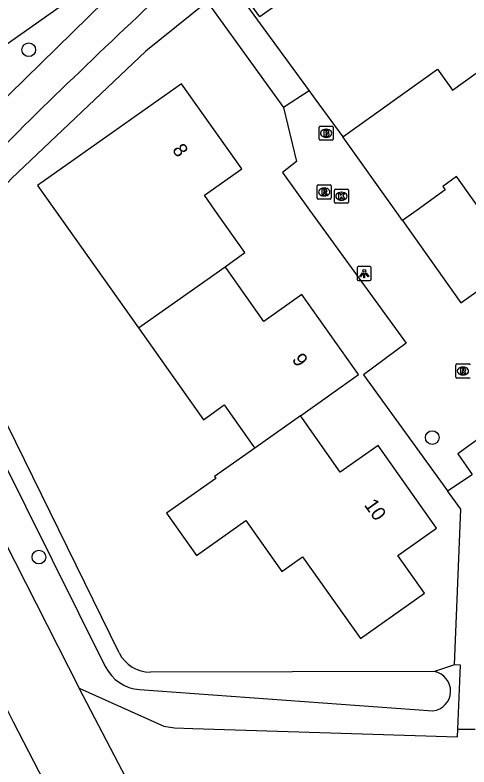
# Model space of a CAD drawing. Extents: x 158461 to 159795, y 387220 to 388672.
# Drawn here: x 159204.5 to 159236.8, y 387710.4 to 387763.8 of the extents above; entities that cross this region are included whole.
import ezdxf

# ---------------------------------------------------------------- set-up
doc = ezdxf.new("R2010")
doc.units = 0
for name, color, linetype in [('IMGEO_Berm_groen', 7, 'Continuous'), ('IMGEO_Boom', 7, 'Continuous'), ('IMGEO_Brandkraan', 7, 'Continuous'), ('IMGEO_Fietspad_gesloten', 7, 'Continuous'), ('IMGEO_Fietspad_open', 7, 'Continuous'), ('IMGEO_Kolk', 7, 'Continuous'), ('IMGEO_Lichtpunt', 7, 'Continuous'), ('IMGEO_Pand', 7, 'Continuous'), ('IMGEO_Pand_nummerreeks', 7, 'Continuous'), ('IMGEO_Rijbaan_lokaal_gesloten', 7, 'Continuous'), ('IMGEO_Rijbaan_lokaal_open', 7, 'Continuous'), ('IMGEO_Rioolput', 7, 'Continuous'), ('IMGEO_Voetpad_halfverhard', 7, 'Continuous'), ('IMGEO_Voetpad_open', 7, 'Continuous'), ('IMGEO_Waterloop', 7, 'Continuous')]:
    doc.layers.add(name, color=color, linetype=linetype)

msp = doc.modelspace()

# ---------------------------------------------------------------- linework, layer by layer
at = {"layer": 'IMGEO_Berm_groen'}
msp.add_lwpolyline([(159235.73, 387717.691), (159234.304, 387717.222)], dxfattribs=at)
at = {"layer": 'IMGEO_Boom'}
for centre in [(159205.5, 387761.384), (159234.149, 387733.837), (159206.219, 387725.353)]:
    msp.add_circle(centre, 0.489, dxfattribs=at)
at = {"layer": 'IMGEO_Brandkraan'}
for p, q in [((159226.186, 387755.954), (159227.038, 387755.954)), ((159226.111, 387755.028), (159226.111, 387755.88)), ((159226.599, 387755.734), (159226.624, 387755.734)), ((159227.112, 387755.88), (159227.112, 387755.028)), ((159227.038, 387754.954), (159226.186, 387754.954)), ((159226.622, 387755.174), (159226.597, 387755.174))]:
    msp.add_line(p, q, dxfattribs=at)
for points in [[(159226.186, 387755.954), (159227.038, 387755.954)], [(159226.111, 387755.028), (159226.111, 387755.88)], [(159226.459, 387755.654), (159226.459, 387755.254), (159226.672, 387755.254)], [(159226.69, 387755.654), (159226.459, 387755.654)], [(159226.638, 387755.573), (159226.584, 387755.573), (159226.584, 387755.497)], [(159226.584, 387755.497), (159226.637, 387755.497)], [(159226.646, 387755.421), (159226.584, 387755.421), (159226.584, 387755.34)], [(159227.112, 387755.88), (159227.112, 387755.028)], [(159227.038, 387754.954), (159226.186, 387754.954)], [(159226.584, 387755.34), (159226.646, 387755.34)]]:
    msp.add_lwpolyline(points, dxfattribs=at)
for centre, radius, start, end in [((159226.188, 387755.878), 0.0765, 91.552, 178.448), ((159226.188, 387755.878), 0.0765, 91.552, 178.448), ((159227.036, 387755.878), 0.0765, 1.552, 88.448), ((159227.036, 387755.878), 0.0765, 1.552, 88.448), ((159226.639, 387755.535), 0.0379, 267.8285, 90.9355), ((159226.647, 387755.38), 0.0404, 269.8759, 90.5077), ((159226.694, 387755.509), 0.145, 59.4692, 91.5367), ((159226.719, 387755.556), 0.0922, 285.5137, 58.1501), ((159226.724, 387755.364), 0.105, 301.3115, 78.989), ((159226.188, 387755.03), 0.0765, 181.552, 268.448), ((159226.188, 387755.03), 0.0765, 181.552, 268.448), ((159226.678, 387755.505), 0.251, 268.6676, 293.5347), ((159227.036, 387755.03), 0.0765, 271.552, 358.448), ((159227.036, 387755.03), 0.0765, 271.552, 358.448)]:
    msp.add_arc(centre, radius, start, end, dxfattribs=at)
for centre, major_axis, ratio, start_param, end_param in [((159226.598, 387755.454), (-0.387, 0.002), 0.722429, 4.712389, 7.853982), ((159226.623, 387755.454), (-0.39, 0.002), 0.717154, 1.570796, 4.712389)]:
    msp.add_ellipse(centre, major_axis=major_axis, ratio=ratio, start_param=start_param, end_param=end_param, dxfattribs=at)
at = {"layer": 'IMGEO_Fietspad_gesloten'}
for points in [[(159203.744, 387726.53), (159209.072, 387716.044)], [(159305.871, 387516.378), (159305.772, 387516.604), (159303.42, 387520.816), (159263.501, 387599.257), (159204.425, 387713.621), (159204.015, 387714.421), (159199.05, 387724.103)], [(159214.062, 387706.489), (159209.072, 387716.044)]]:
    msp.add_lwpolyline(points, dxfattribs=at)
at = {"layer": 'IMGEO_Fietspad_open'}
msp.add_lwpolyline([(159214.491, 387768.328), (159213.131, 387767.053), (159199.59, 387753.792), (159198.894, 387753.089), (159198.822, 387753.027)], dxfattribs=at)
for centre, radius, start, end in [((159441.931, 387520.228), 334.072, 132.45033, 134.17723), ((159347.221, 387613.579), 201.141, 133.35949, 138.92324)]:
    msp.add_arc(centre, radius, start, end, dxfattribs=at)
at = {"layer": 'IMGEO_Kolk'}
for p, q in [((159227.199, 387750.556), (159227.199, 387751.408)), ((159227.274, 387751.482), (159228.126, 387751.482)), ((159227.687, 387751.262), (159227.712, 387751.262)), ((159228.2, 387751.408), (159228.2, 387750.556)), ((159227.71, 387750.702), (159227.685, 387750.702)), ((159228.126, 387750.482), (159227.274, 387750.482))]:
    msp.add_line(p, q, dxfattribs=at)
for points in [[(159227.199, 387750.556), (159227.199, 387751.408)], [(159227.274, 387751.482), (159228.126, 387751.482)], [(159227.52, 387751.182), (159227.643, 387751.182), (159227.643, 387751.031), (159227.773, 387751.182), (159227.937, 387751.182), (159227.791, 387751.031), (159227.944, 387750.782), (159227.792, 387750.782), (159227.707, 387750.946), (159227.643, 387750.879), (159227.643, 387750.782), (159227.52, 387750.782), (159227.52, 387751.182)], [(159228.2, 387751.408), (159228.2, 387750.556)], [(159228.126, 387750.482), (159227.274, 387750.482)]]:
    msp.add_lwpolyline(points, dxfattribs=at)
for centre, start, end in [((159227.276, 387751.406), 91.552, 178.448), ((159227.276, 387751.406), 91.552, 178.448), ((159228.124, 387751.406), 1.552, 88.448), ((159228.124, 387751.406), 1.552, 88.448), ((159227.276, 387750.558), 181.552, 268.448), ((159227.276, 387750.558), 181.552, 268.448), ((159228.124, 387750.558), 271.552, 358.448), ((159228.124, 387750.558), 271.552, 358.448)]:
    msp.add_arc(centre, 0.0765, start, end, dxfattribs=at)
for centre, major_axis, ratio, start_param, end_param in [((159227.686, 387750.982), (-0.387, 0.002), 0.722429, 4.712389, 7.853982), ((159227.711, 387750.982), (-0.39, 0.002), 0.717154, 1.570796, 4.712389)]:
    msp.add_ellipse(centre, major_axis=major_axis, ratio=ratio, start_param=start_param, end_param=end_param, dxfattribs=at)
at = {"layer": 'IMGEO_Lichtpunt'}
for p, q in [((159228.821, 387745.886), (159228.821, 387745.079)), ((159228.821, 387745.886), (159228.821, 387745.079)), ((159229.723, 387745.981), (159228.915, 387745.981)), ((159229.723, 387745.981), (159228.915, 387745.981)), ((159229.817, 387745.079), (159229.817, 387745.886)), ((159229.817, 387745.079), (159229.817, 387745.886)), ((159228.915, 387744.985), (159229.723, 387744.985)), ((159228.915, 387744.985), (159229.723, 387744.985))]:
    msp.add_line(p, q, dxfattribs=at)
for points in [[(159229.195, 387745.55), (159229.234, 387745.522), (159229.046, 387745.26), (159229.008, 387745.287), (159229.195, 387745.55)], [(159229.297, 387745.502), (159229.344, 387745.502), (159229.344, 387745.18), (159229.297, 387745.18), (159229.297, 387745.502)], [(159229.407, 387745.522), (159229.445, 387745.549), (159229.632, 387745.287), (159229.593, 387745.259), (159229.407, 387745.522)]]:
    msp.add_lwpolyline(points, dxfattribs=at)
msp.add_circle((159229.32, 387745.684), 0.0994, dxfattribs=at)
for centre, start, end in [((159228.915, 387745.886), 90, 180), ((159228.915, 387745.886), 90, 180), ((159229.723, 387745.886), 0, 90), ((159229.723, 387745.886), 0, 90), ((159228.915, 387745.079), 180, 270), ((159228.915, 387745.079), 180, 270), ((159229.723, 387745.079), 270, 0), ((159229.723, 387745.079), 270, 360)]:
    msp.add_arc(centre, 0.0946, start, end, dxfattribs=at)
at = {"layer": 'IMGEO_Pand'}
for points in [[(159224.026, 387765.272), (159221.912, 387763.731), (159220.309, 387765.93), (159222.423, 387767.471), (159224.026, 387765.272)], [(159227.788, 387755.197), (159234.513, 387760.012), (159235.582, 387758.518), (159238.444, 387760.567), (159238.638, 387760.706)], [(159219.44, 387745.978), (159220.851, 387746.977), (159218.713, 387750), (159217.973, 387751.046), (159220.621, 387752.92), (159216.34, 387758.971), (159209.096, 387753.846), (159206.13, 387751.748), (159208.321, 387748.651), (159213.29, 387741.626)], [(159232.039, 387749.261), (159231.51, 387750), (159227.788, 387755.197)], [(159242.699, 387755.037), (159243.735, 387753.59), (159238.722, 387750), (159237.962, 387749.456), (159237.572, 387750), (159236.047, 387752.13), (159235.872, 387752.374), (159234.896, 387751.676), (159235.071, 387751.431), (159233.071, 387750), (159232.039, 387749.261)], [(159213.29, 387741.626), (159219.44, 387745.978)], [(159224.79, 387735.39), (159228.92, 387738.31), (159224.896, 387743.997), (159222.194, 387742.085), (159219.527, 387745.855), (159219.44, 387745.978)], [(159213.29, 387741.626), (159217.899, 387735.111), (159219.374, 387736.154), (159221.405, 387733.283), (159221.54, 387733.092)], [(159221.54, 387733.092), (159218.685, 387731.074), (159218.777, 387730.944), (159215.287, 387728.476), (159217.411, 387725.473), (159220.901, 387727.942), (159223.459, 387724.327), (159224.942, 387725.377), (159229.048, 387719.576), (159233.601, 387722.797), (159231.707, 387725.473), (159234.449, 387727.414), (159230.297, 387733.283), (159227.62, 387731.389), (159224.935, 387735.185), (159224.79, 387735.39)], [(159224.79, 387735.39), (159221.54, 387733.092)]]:
    msp.add_lwpolyline(points, dxfattribs=at)
at = {"layer": 'IMGEO_Rijbaan_lokaal_gesloten'}
msp.add_lwpolyline([(159196.748, 387756.729), (159202.425, 387760.735), (159214.068, 387768.944)], dxfattribs=at)
at = {"layer": 'IMGEO_Rijbaan_lokaal_open'}
for points in [[(159232.039, 387749.261), (159236.184, 387743.412), (159238.603, 387745.147), (159240.605, 387744.76), (159247.948, 387750), (159265.053, 387762.206), (159265.409, 387764.288), (159291.33, 387782.791), (159291.199, 387784.46), (159296.92, 387788.616), (159298.653, 387788.087), (159304.712, 387792.385), (159307.252, 387792.251), (159320.165, 387774.132), (159324.208, 387773.477), (159343.063, 387787.123), (159343.181, 387788.954)], [(159277.893, 387764.497), (159277.605, 387762.555), (159274.948, 387760.678), (159277.299, 387757.343), (159266.972, 387750), (159257.945, 387743.581), (159255.655, 387746.817), (159253.197, 387745.09), (159251.126, 387745.348), (159238.707, 387736.519), (159238.451, 387734.477), (159235.953, 387732.682), (159236.986, 387731.212)], [(159225.4, 387758.477), (159223.591, 387757.291)], [(159225.4, 387758.477), (159225.842, 387757.87), (159227.788, 387755.197)], [(159223.591, 387757.291), (159224.515, 387753.447), (159223.511, 387752.661), (159225.442, 387750), (159232.294, 387740.557), (159229.26, 387738.298), (159235.227, 387730.066)], [(159235.227, 387730.066), (159236.986, 387731.212)]]:
    msp.add_lwpolyline(points, dxfattribs=at)
at = {"layer": 'IMGEO_Rioolput'}
for p, q in [((159225.977, 387750.857), (159225.977, 387751.709)), ((159226.052, 387751.783), (159226.904, 387751.783)), ((159226.978, 387751.709), (159226.978, 387750.857)), ((159226.465, 387751.563), (159226.49, 387751.563)), ((159226.904, 387750.783), (159226.052, 387750.783)), ((159226.488, 387751.003), (159226.463, 387751.003)), ((159235.825, 387738.141), (159235.825, 387738.993)), ((159235.9, 387739.067), (159236.752, 387739.067)), ((159236.313, 387738.847), (159236.338, 387738.847)), ((159236.752, 387738.067), (159235.9, 387738.067)), ((159236.336, 387738.287), (159236.311, 387738.287))]:
    msp.add_line(p, q, dxfattribs=at)
for points in [[(159225.977, 387750.857), (159225.977, 387751.709)], [(159226.052, 387751.783), (159226.904, 387751.783)], [(159226.978, 387751.709), (159226.978, 387750.857)], [(159226.566, 387751.481), (159226.314, 387751.483), (159226.314, 387751.083)], [(159226.314, 387751.083), (159226.438, 387751.083), (159226.438, 387751.245), (159226.449, 387751.245)], [(159226.492, 387751.402), (159226.438, 387751.402), (159226.438, 387751.321)], [(159226.438, 387751.321), (159226.49, 387751.321)], [(159226.496, 387751.216), (159226.567, 387751.083), (159226.707, 387751.083), (159226.642, 387751.209)], [(159226.904, 387750.783), (159226.052, 387750.783)], [(159235.825, 387738.141), (159235.825, 387738.993)], [(159235.9, 387739.067), (159236.752, 387739.067)], [(159236.414, 387738.765), (159236.162, 387738.767), (159236.162, 387738.367)], [(159236.162, 387738.367), (159236.286, 387738.367), (159236.286, 387738.529), (159236.297, 387738.529)], [(159236.34, 387738.686), (159236.286, 387738.686), (159236.286, 387738.605)], [(159236.286, 387738.605), (159236.338, 387738.605)], [(159236.344, 387738.5), (159236.415, 387738.367), (159236.555, 387738.367), (159236.49, 387738.493)], [(159236.752, 387738.067), (159235.9, 387738.067)]]:
    msp.add_lwpolyline(points, dxfattribs=at)
for centre, radius, start, end in [((159226.054, 387751.707), 0.0765, 91.552, 178.448), ((159226.054, 387751.707), 0.0765, 91.552, 178.448), ((159226.902, 387751.707), 0.0765, 1.552, 88.448), ((159226.902, 387751.707), 0.0765, 1.552, 88.448), ((159226.448, 387751.192), 0.0533, 26.0293, 88.6989), ((159226.474, 387751.51), 0.19, 274.7715, 282.9687), ((159226.498, 387751.306), 0.0964, 77.0061, 93.1865), ((159226.512, 387751.363), 0.0378, 276.6634, 79.6772), ((159226.565, 387751.371), 0.109, 350.3612, 89.416), ((159226.563, 387751.371), 0.112, 277.5842, 350.9817), ((159226.547, 387751.156), 0.108, 29.5134, 73.7905), ((159226.054, 387750.859), 0.0765, 181.552, 268.448), ((159226.054, 387750.859), 0.0765, 181.552, 268.448), ((159226.902, 387750.859), 0.0765, 271.552, 358.448), ((159226.902, 387750.859), 0.0765, 271.552, 358.448), ((159235.902, 387738.991), 0.0765, 91.552, 178.448), ((159235.902, 387738.991), 0.0765, 91.552, 178.448), ((159236.75, 387738.991), 0.0765, 1.552, 88.448), ((159236.75, 387738.991), 0.0765, 1.552, 88.448), ((159236.296, 387738.476), 0.0533, 26.0293, 88.6989), ((159236.322, 387738.794), 0.19, 274.7715, 282.9687), ((159236.346, 387738.59), 0.0964, 77.0061, 93.1865), ((159236.36, 387738.647), 0.0378, 276.6634, 79.6772), ((159236.413, 387738.655), 0.109, 350.3612, 89.416), ((159236.411, 387738.655), 0.112, 277.5842, 350.9817), ((159236.395, 387738.44), 0.108, 29.5134, 73.7905), ((159235.902, 387738.143), 0.0765, 181.552, 268.448), ((159235.902, 387738.143), 0.0765, 181.552, 268.448), ((159236.75, 387738.143), 0.0765, 271.552, 358.448), ((159236.75, 387738.143), 0.0765, 271.552, 358.448)]:
    msp.add_arc(centre, radius, start, end, dxfattribs=at)
for centre, major_axis, ratio, start_param, end_param in [((159226.464, 387751.283), (-0.387, 0.002), 0.722429, 4.712389, 7.853982), ((159226.489, 387751.283), (-0.39, 0.002), 0.717154, 1.570796, 4.712389), ((159236.312, 387738.567), (-0.387, 0.002), 0.722429, 4.712389, 7.853982), ((159236.337, 387738.567), (-0.39, 0.002), 0.717154, 1.570796, 4.712389)]:
    msp.add_ellipse(centre, major_axis=major_axis, ratio=ratio, start_param=start_param, end_param=end_param, dxfattribs=at)
at = {"layer": 'IMGEO_Voetpad_halfverhard'}
msp.add_lwpolyline([(159209.072, 387716.044), (159215.088, 387713.348), (159215.858, 387713.235), (159217.158, 387713.181), (159235.947, 387712.585), (159235.969, 387713.133)], dxfattribs=at)
at = {"layer": 'IMGEO_Voetpad_open'}
for points in [[(159219.866, 387766.077), (159225.4, 387758.477)], [(159218.155, 387764.796), (159213.819, 387761.288), (159204.282, 387752.237), (159202.211, 387750), (159197.458, 387744.641)], [(159218.155, 387764.796), (159223.591, 387757.291)], [(159235.73, 387717.691), (159236.179, 387728.753), (159235.227, 387730.066)], [(159235.969, 387713.133), (159236.15, 387717.664), (159235.73, 387717.691)], [(159235.969, 387713.133), (159237.189, 387713.141)]]:
    msp.add_lwpolyline(points, dxfattribs=at)
at = {"layer": 'IMGEO_Waterloop'}
for points in [[(159211.918, 387718.548), (159199.04, 387744.753)], [(159197.72, 387744.115), (159210.934, 387717.576)], [(159234.304, 387717.222), (159214.14, 387717.171)], [(159213.363, 387715.947), (159234.192, 387714.442)]]:
    msp.add_lwpolyline(points, dxfattribs=at)
for centre, radius, start, end in [((159214.135, 387719.644), 2.473, 206.3051, 270.1209), ((159213.574, 387718.886), 2.947, 206.4011, 265.9036), ((159234.046, 387715.84), 1.406, 275.9436, 79.4423)]:
    msp.add_arc(centre, radius, start, end, dxfattribs=at)

# ---------------------------------------------------------------- texts
at = {"layer": 'IMGEO_Pand_nummerreeks'}
for s, rotation, p in [('8', 305.2768, (159215.646, 387754.273)), ('9', 305.2825, (159224.144, 387739.382)), ('10', 305.2768, (159229.273, 387729.053))]:
    msp.add_text(s, height=1, rotation=rotation, dxfattribs=at).set_placement(p)

doc.saveas('drawing.dxf')
